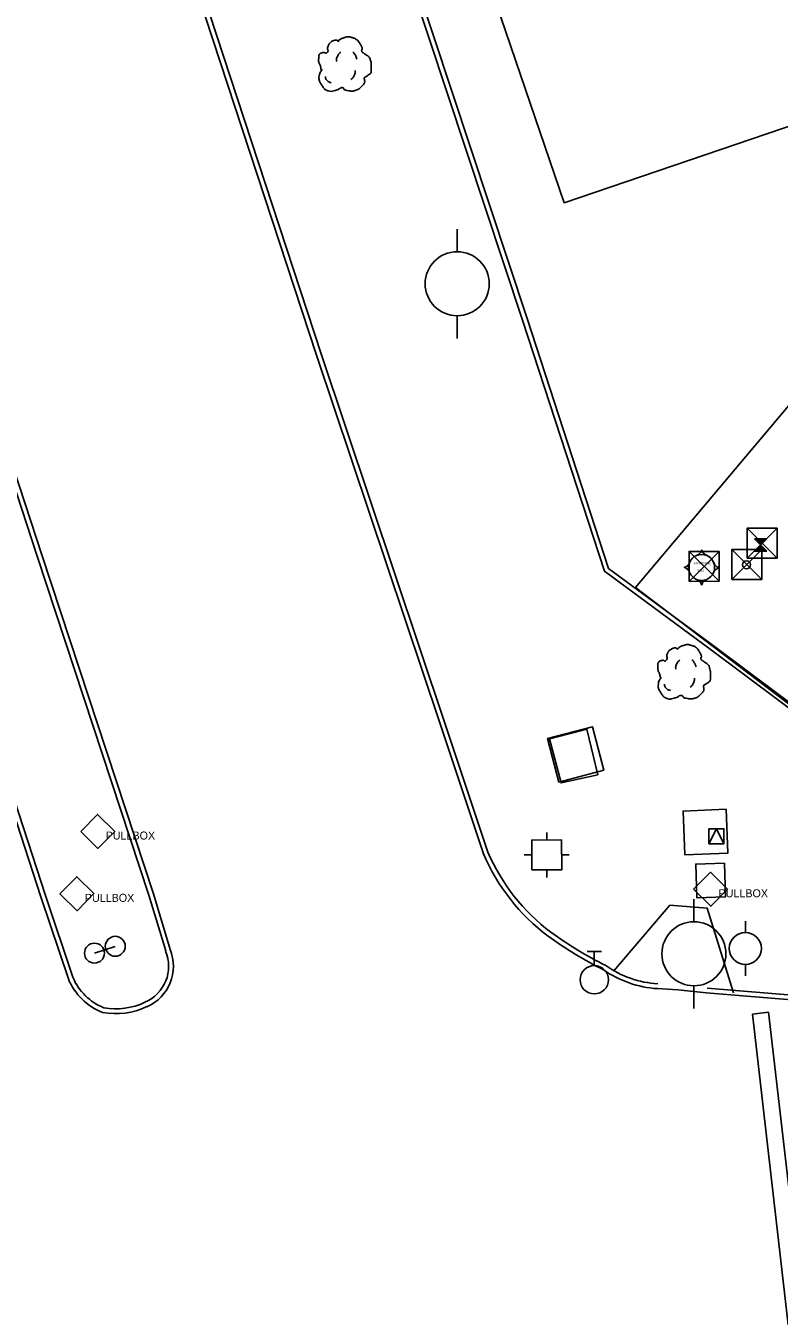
# Model space of a CAD drawing. Extents: x 2145380 to 2156929, y 139568 to 149130.
# Drawn here: x 2147292.3 to 2147386.4, y 143177.2 to 143338.4 of the extents above; entities that cross this region are included whole.
import ezdxf

# ---------------------------------------------------------------- set-up
doc = ezdxf.new("R2010")
doc.units = 0
for name, color, linetype in [('Default', 7, 'Continuous'), ('TOPO_Asphalt', 7, 'Continuous'), ('TOPO_Building', 7, 'Continuous'), ('TOPO_Concrete', 7, 'Continuous'), ('TOPO_Curb Back', 7, 'Continuous'), ('TOPO_Filler Cap', 7, 'Continuous'), ('TOPO_Fuel Pump', 7, 'Continuous'), ('TOPO_Misc', 7, 'Continuous'), ('TOPO_Misc Line', 7, 'Continuous'), ('TOPO_Monitoring Well', 7, 'Continuous'), ('TOPO_Power Pole', 7, 'Continuous'), ('TOPO_Power Pullbox', 7, 'Continuous'), ('TOPO_Sidewalk', 7, 'Continuous'), ('TOPO_Sign', 7, 'Continuous'), ('TOPO_Traffic Signal', 7, 'Continuous'), ('TOPO_Tree', 7, 'Continuous'), ('TOPO_Water Valve', 7, 'Continuous')]:
    doc.layers.add(name, color=color, linetype=linetype)

# ---------------------------------------------------------------- blocks, each defined once
blk = doc.blocks.new('POWPOL')
at = {"layer": 'TOPO_Power Pole'}
for p, q in [((0, 10.16), (0, 17.34)), ((0, -10.16), (0, -17.34))]:
    blk.add_line(p, q, dxfattribs=at)
blk.add_circle((0, 0), 10.16, dxfattribs=at)
blk = doc.blocks.new('TRFSIG')
at = {"layer": 'TOPO_Traffic Signal'}
for p, q in [((0.04, 4.66), (0.04, 7.04)), ((-4.7, -0.09), (-7.08, -0.09)), ((4.79, -0.09), (7.17, -0.09)), ((0.04, -4.83), (0.04, -7.22))]:
    blk.add_line(p, q, dxfattribs=at)
blk.add_lwpolyline([(-4.7, -4.85), (4.81, -4.83), (4.79, 4.67), (-4.72, 4.66), (-4.7, -4.85)], dxfattribs=at)
blk = doc.blocks.new('TREE')
at = {"layer": 'TOPO_Tree'}
for points in [[(-14.07, -0.4), (-14.17, 0.5), (-14.37, 1.38), (-14.6, 2.25), (-14.84, 3.17), (-15.47, 3.96), (-15.66, 4.9), (-15.8, 5.59), (-15.71, 6.31), (-15.66, 7.01), (-15.6, 7.91), (-15.72, 8.8), (-15.13, 9.66), (-14.62, 10.42), (-13.76, 10.49), (-13.02, 10.72), (-12.18, 10.98), (-11.06, 10), (-10.37, 10.72), (-9.4, 11.74), (-10.29, 13.28), (-9.84, 14.42), (-9.56, 15.15), (-9.32, 15.89), (-8.78, 16.54), (-8.18, 17.26), (-7.5, 17.68), (-6.67, 18.13), (-6.14, 18.41), (-5.61, 18.61), (-5.08, 18.66), (-4.55, 18.71), (-4.02, 18.54), (-3.49, 18.13)], [(-3.49, 17.6), (-3.07, 18.27), (-2.58, 18.8), (-1.9, 19.19), (-1.05, 19.68), (-0.19, 19.96), (0.74, 20.24), (1.62, 20.51), (2.51, 20.82), (3.39, 20.77), (4.1, 20.73), (4.8, 20.47), (5.51, 20.24), (6.43, 19.95), (7.32, 19.73), (8.15, 19.19), (9.36, 18.4), (10.02, 17.21), (10.8, 16.01), (11.24, 15.33), (11.58, 14.62), (11.86, 13.89), (12.17, 13.08), (11.37, 12.02), (11.86, 11.25), (12, 11.03), (12.18, 10.86), (12.39, 10.72), (12.91, 10.35), (13.45, 10.02), (13.97, 9.66), (14.7, 9.16), (15.41, 8.68), (16.09, 8.07), (16.7, 7.53), (16.93, 6.73), (17.15, 5.95), (17.59, 4.38), (17.71, 2.77), (17.68, 1.19), (17.65, -0.25), (17.83, -2.22), (16.62, -3.04), (15.47, -3.83), (14.31, -4.58), (13.16, -5.35)], [(-4.21, 5.09), (-4.46, 6.09), (-4.3, 7.21), (-3.84, 8.21), (-3.33, 9.34), (-2.71, 10.27), (-1.64, 10.97)], [(5.89, 11.15), (6.5, 10.68), (6.96, 10.17), (7.36, 9.5), (7.93, 8.56), (8.31, 7.6), (8.46, 6.56)], [(13.16, -5.34), (13.25, -5.81), (13.36, -6.28), (13.45, -6.75), (13.76, -8.52), (12.24, -10.03), (10.8, -11.51), (9.98, -12.34), (9.13, -12.77), (8.15, -13.1), (5.97, -13.83), (3.32, -13.56), (1.27, -13.1), (0.49, -12.92), (-0.06, -11.44), (-0.84, -11.51), (-2.04, -11.61), (-3.28, -12.78), (-4.55, -13.1), (-6.06, -13.47), (-7.77, -14.03), (-9.31, -13.62), (-11.36, -13.09), (-12.84, -11.41), (-14.07, -9.39), (-15.32, -7.35), (-15.61, -5.13), (-15.13, -3.04), (-14.87, -1.89), (-13.91, -0.75), (-13.54, 0.13)], [(-11.38, -4.46), (-11.47, -5.41), (-11.03, -6.32), (-10.09, -7.22), (-9.3, -7.97), (-8.49, -8.26), (-7.7, -8.14)], [(4.79, -6.29), (5.71, -5.66), (6.3, -4.92), (6.81, -3.91), (7.36, -2.81), (7.63, -1.7), (7.54, -0.6)]]:
    blk.add_open_spline(points, degree=3, dxfattribs=at)
blk = doc.blocks.new('POST')
at = {"layer": 'TOPO_Misc'}
for start, end in [(90, 180), (180, 270), (360, 90), (270, 0)]:
    blk.add_arc((-0.01, 0.03), 3.16, start, end, dxfattribs=at)
blk = doc.blocks.new('pulbox')
at = {"layer": 'Default'}
blk.add_lwpolyline([(-5.38, -0.01), (-0.02, 5.42), (5.4, 0.06), (0.05, -5.36), (-5.38, -0.01)], dxfattribs=at)
blk.add_text('PULLBOX', height=2.54, dxfattribs=at).set_placement((2.54, -2.54))
blk = doc.blocks.new('MONW')
at = {"layer": 'Default'}
for points in [[(-0.178, 0.372), (-0.138, 0.389), (-0.101, 0.407), (-0.063, 0.443), (-0.039, 0.474), (-0.018, 0.503), (-0.009, 0.523), (0.003, 0.552), (0.018, 0.515), (0.031, 0.488), (0.046, 0.47), (0.07, 0.441), (0.087, 0.425), (0.108, 0.407), (0.134, 0.396), (0.164, 0.385)], [(-0.369, 0.18), (-0.386, 0.141), (-0.405, 0.103), (-0.441, 0.066), (-0.471, 0.041), (-0.501, 0.021), (-0.52, 0.011), (-0.55, 0), (-0.513, -0.015), (-0.486, -0.028), (-0.467, -0.043), (-0.439, -0.068), (-0.422, -0.085), (-0.405, -0.106), (-0.394, -0.132), (-0.383, -0.162)], [(0.371, -0.189), (0.388, -0.149), (0.407, -0.111), (0.443, -0.074), (0.473, -0.05), (0.503, -0.029), (0.522, -0.019), (0.552, -0.008), (0.515, 0.007), (0.488, 0.02), (0.469, 0.035), (0.441, 0.06), (0.424, 0.077), (0.407, 0.098), (0.396, 0.124), (0.385, 0.154)], [(-0.178, -0.373), (-0.138, -0.39), (-0.101, -0.408), (-0.063, -0.444), (-0.039, -0.475), (-0.018, -0.504), (-0.009, -0.524), (0.003, -0.553), (0.018, -0.516), (0.031, -0.489), (0.046, -0.471), (0.07, -0.442), (0.087, -0.426), (0.108, -0.408), (0.134, -0.397), (0.164, -0.386)]]:
    blk.add_lwpolyline(points, dxfattribs=at)
blk.add_circle((0, 0), 0.413, dxfattribs=at)
for s, p in [('MONITORING', (-0.249, 0.103)), ('WELL', (-0.136, -0.124))]:
    blk.add_text(s, height=0.0607, dxfattribs=at).set_placement(p)
blk = doc.blocks.new('WATVAL')
at = {"layer": 'Default'}
for p, q in [((-2.25, 9), (2.25, 9)), ((0, 4.5), (0, 9))]:
    blk.add_line(p, q, dxfattribs=at)
blk.add_circle((0, 0), 4.5, dxfattribs=at)
blk = doc.blocks.new('POINT_DISPLAY')
at = {"layer": 'Default'}
blk.add_line((0, 0), (0, 0), dxfattribs=at)
blk = doc.blocks.new('gVALVE')
at = {"layer": 'Default'}
for p, q in [((0.65, 0.65), (-0.65, 0.65)), ((-0.65, -0.65), (0.65, 0.65)), ((0.65, -0.65), (-0.65, 0.65)), ((0.57, 0.62), (-0.58, 0.62)), ((-0.58, 0.62), (0, 0.04)), ((-0.51, 0.6), (0.52, 0.6)), ((0, 0.08), (-0.51, 0.6)), ((-0.44, 0.58), (0.45, 0.57)), ((0, 0.13), (-0.44, 0.58)), ((-0.37, 0.55), (0.37, 0.54)), ((0.01, 0.19), (-0.37, 0.55)), ((-0.3, 0.52), (0.3, 0.52)), ((0, 0.23), (-0.3, 0.52)), ((-0.22, 0.49), (0.23, 0.5)), ((0.01, 0.29), (-0.22, 0.49)), ((-0.15, 0.46), (0.15, 0.47)), ((0.01, 0.33), (-0.15, 0.46)), ((-0.08, 0.44), (0.09, 0.45)), ((0.01, 0.36), (-0.08, 0.44)), ((-0.04, 0.42), (0.05, 0.43)), ((0.01, 0.39), (-0.04, 0.42)), ((0, 0.04), (0.58, 0.62)), ((0.51, 0.6), (0, 0.08)), ((0.45, 0.57), (0, 0.13)), ((0.3, 0.52), (0, 0.23)), ((0.05, 0.43), (0, 0.41)), ((0.37, 0.54), (0.01, 0.19)), ((0.23, 0.49), (0.01, 0.29)), ((0.15, 0.47), (0.01, 0.33)), ((0.1, 0.45), (0.01, 0.36)), ((0.06, 0.43), (0.01, 0.39)), ((0.09, 0.45), (0.06, 0.43)), ((0.15, 0.47), (0.1, 0.45)), ((0.23, 0.5), (0.15, 0.47)), ((0.3, 0.52), (0.23, 0.49)), ((0.37, 0.54), (0.3, 0.52)), ((0.45, 0.57), (0.37, 0.54)), ((0.52, 0.6), (0.45, 0.57)), ((0.58, 0.62), (0.51, 0.6)), ((-0.65, -0.65), (0.65, -0.65)), ((-0.59, -0.62), (0, -0.03)), ((-0.59, -0.62), (-0.54, -0.6)), ((0.59, -0.63), (-0.59, -0.62)), ((-0.54, -0.6), (0, -0.08)), ((-0.54, -0.6), (-0.48, -0.58)), ((0.53, -0.6), (-0.54, -0.6)), ((-0.48, -0.58), (0, -0.13)), ((-0.47, -0.58), (-0.39, -0.55)), ((0.47, -0.58), (-0.47, -0.58)), ((-0.39, -0.55), (0, -0.18)), ((-0.39, -0.55), (-0.32, -0.53)), ((0.4, -0.55), (-0.39, -0.55)), ((-0.32, -0.53), (0, -0.22)), ((-0.31, -0.53), (-0.24, -0.51)), ((0.32, -0.53), (-0.31, -0.53)), ((-0.24, -0.51), (0, -0.28)), ((-0.24, -0.51), (-0.17, -0.49)), ((0.25, -0.5), (-0.24, -0.51)), ((-0.17, -0.49), (-0.01, -0.32)), ((-0.17, -0.48), (-0.1, -0.46)), ((0.18, -0.48), (-0.17, -0.48)), ((-0.1, -0.46), (-0.01, -0.37)), ((-0.09, -0.46), (-0.05, -0.44)), ((0.11, -0.46), (-0.09, -0.46)), ((-0.05, -0.44), (-0.01, -0.41)), ((0.04, -0.44), (-0.04, -0.44)), ((-0.01, -0.32), (0.18, -0.48)), ((-0.01, -0.37), (0.11, -0.46)), ((-0.01, -0.41), (0.04, -0.44)), ((0, -0.03), (0.59, -0.63)), ((0, -0.08), (0.53, -0.6)), ((0, -0.13), (0.47, -0.58)), ((0, -0.18), (0.4, -0.55)), ((0, -0.22), (0.32, -0.53)), ((0, -0.28), (0.25, -0.5))]:
    blk.add_line(p, q, dxfattribs=at)
blk.add_blockref('POINT_DISPLAY', (0, 0), dxfattribs=at)

msp = doc.modelspace()

# ---------------------------------------------------------------- linework, layer by layer
at = {"layer": 'TOPO_Asphalt'}
msp.add_lwpolyline([(2147371.15, 143218.12), (2147373.71, 143217.97), (2147377.31, 143217.58)], dxfattribs=at)
at = {"layer": 'TOPO_Building'}
msp.add_lwpolyline([(2147396.47, 143380.5), (2147343.76, 143362.56), (2147359.52, 143316.28), (2147412.23, 143334.22)], close=True, dxfattribs=at)
at = {"layer": 'TOPO_Concrete'}
for points in [[(2147407.53, 143238.47), (2147436.9, 143273.89), (2147397.78, 143303.06), (2147368.44, 143268.23), (2147407.53, 143238.47)], [(2147358.84, 143243.92), (2147357.43, 143249.36), (2147363.05, 143250.82), (2147364.46, 143245.38), (2147358.84, 143243.92)], [(2147363.71, 143244.8), (2147359.13, 143243.8), (2147357.68, 143249.32), (2147362.33, 143250.51), (2147363.71, 143244.8)], [(2147374.59, 143234.83), (2147374.36, 143240.29), (2147379.73, 143240.51), (2147379.96, 143235.05), (2147374.59, 143234.83)], [(2147379.55, 143233.78), (2147379.67, 143229.58), (2147376.08, 143229.47), (2147375.95, 143233.67), (2147379.55, 143233.78)]]:
    msp.add_lwpolyline(points, dxfattribs=at)
at = {"layer": 'TOPO_Curb Back'}
for p, q in [((2147279.68, 143314.95), (2147293.72, 143272.12)), ((2147280.25, 143315.14), (2147294.29, 143272.31)), ((2147294.19, 143229.56), (2147278.21, 143278.52)), ((2147294.76, 143229.75), (2147278.78, 143278.69)), ((2147293.72, 143272.12), (2147307.65, 143229.79)), ((2147294.29, 143272.31), (2147308.22, 143229.97)), ((2147297.61, 143219.32), (2147294.19, 143229.56)), ((2147298.17, 143219.53), (2147294.76, 143229.75)), ((2147307.65, 143229.79), (2147309.76, 143222.81)), ((2147308.22, 143229.97), (2147310.32, 143223.01))]:
    msp.add_line(p, q, dxfattribs=at)
for points in [[(2147517.02, 143239.1), (2147482.38, 143238.34), (2147439.31, 143237.85), (2147408.44, 143237.55), (2147377.76, 143260.51), (2147364.56, 143270.24), (2147354.31, 143301.63), (2147333.23, 143365.36), (2147326.82, 143385.52), (2147326.46, 143411.36), (2147326.23, 143416.01)], [(2147517, 143239.7), (2147482.37, 143238.94), (2147439.3, 143238.45), (2147408.63, 143238.16), (2147378.12, 143260.99), (2147365.07, 143270.61), (2147354.88, 143301.82), (2147333.8, 143365.55), (2147327.41, 143385.62), (2147327.06, 143411.38), (2147326.83, 143415.99)], [(2147293.8, 143402.61), (2147300.88, 143382.17), (2147313.77, 143342.42), (2147328.59, 143297.23), (2147344.02, 143251.18), (2147349.44, 143234.94)], [(2147294.36, 143402.8), (2147301.45, 143382.36), (2147314.34, 143342.61), (2147329.16, 143297.42), (2147344.59, 143251.38), (2147350, 143235.15)], [(2147377.36, 143218.18), (2147403.62, 143216.02), (2147433.38, 143213.03), (2147447.37, 143211.78), (2147492.61, 143210.69), (2147509.18, 143209.95)], [(2147377.31, 143217.58), (2147403.56, 143215.42), (2147433.33, 143212.43), (2147447.34, 143211.18), (2147492.58, 143210.09), (2147509.15, 143209.36)]]:
    msp.add_lwpolyline(points, dxfattribs=at)
for centre, radius, start, end in [((2147372.8, 143244.95), 25.41, 203.189, 232.9922), ((2147372.8, 143244.95), 24.81, 203.246, 232.9766), ((2147387.43, 143266.29), 51.27, 234.2901, 243.3365), ((2147387.43, 143266.29), 50.67, 234.2978, 243.3859), ((2147305.2, 143220.92), 4.93, 293.547, 22.5261), ((2147305.2, 143220.92), 5.53, 293.6433, 22.2073), ((2147372.02, 143231.35), 12.67, 234.8757, 266.317), ((2147304.67, 143222.26), 7.65, 202.6402, 248.5564), ((2147304.67, 143222.26), 7.05, 202.8146, 248.092), ((2147372.02, 143231.35), 13.27, 235.07, 266.317), ((2147303.54, 143224.1), 8.51, 259.8549, 295.3006), ((2147303.54, 143224.1), 9.11, 259.4676, 295.2436)]:
    msp.add_arc(centre, radius, start, end, dxfattribs=at)
at = {"layer": 'TOPO_Filler Cap'}
msp.add_circle((2147382.29, 143271.06), 0.5, dxfattribs=at)
at = {"layer": 'TOPO_Misc'}
for p, q in [((2147382.36, 143275.62), (2147386.11, 143271.88)), ((2147375.12, 143272.73), (2147378.87, 143268.99)), ((2147380.47, 143272.97), (2147384.22, 143269.23))]:
    msp.add_line(p, q, dxfattribs=at)
for points in [[(2147382.37, 143271.88), (2147386.11, 143271.88), (2147386.11, 143275.63), (2147382.36, 143275.62), (2147382.37, 143271.88), (2147386.11, 143275.63)], [(2147375.13, 143268.98), (2147378.87, 143268.99), (2147378.86, 143272.73), (2147375.12, 143272.73), (2147375.13, 143268.98), (2147378.86, 143272.73)], [(2147380.47, 143269.22), (2147384.22, 143269.23), (2147384.21, 143272.97), (2147380.47, 143272.97), (2147380.47, 143269.22), (2147384.21, 143272.97)], [(2147377.6, 143236.21), (2147379.47, 143236.21), (2147379.47, 143238.09), (2147377.6, 143238.08), (2147377.6, 143236.21), (2147378.54, 143238.08), (2147379.47, 143236.21)]]:
    msp.add_lwpolyline(points, dxfattribs=at)
at = {"layer": 'TOPO_Misc Line'}
msp.add_lwpolyline([(2147389.93, 143172.79), (2147385.03, 143215.16), (2147383.04, 143214.93), (2147388.02, 143171.39)], close=True, dxfattribs=at)
at = {"layer": 'TOPO_Sidewalk'}
msp.add_lwpolyline([(2147365.73, 143220.35), (2147372.72, 143228.52), (2147377.39, 143228.18), (2147380.68, 143217.6)], dxfattribs=at)
at = {"layer": 'TOPO_Sign'}
msp.add_lwpolyline([(2147300.87, 143222.53), (2147303.47, 143223.39)], dxfattribs=at)

# ---------------------------------------------------------------- block references
at = {"layer": 'TOPO_Fuel Pump', "xscale": 1.1811000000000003, "yscale": 1.1811000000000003}
msp.add_blockref('gVALVE', (2147384.07, 143273.53), dxfattribs=at)
msp.add_blockref('gVALVE', (2147384.07, 143273.53), dxfattribs=at)
at = {"layer": 'TOPO_Misc', "xscale": 0.39370000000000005, "yscale": 0.3937000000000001}
for p in [(2147303.47, 143223.39), (2147300.87, 143222.53)]:
    msp.add_blockref('POST', p, dxfattribs=at)
at = {"layer": 'TOPO_Monitoring Well', "xscale": 3.9370000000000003, "yscale": 3.9370000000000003}
msp.add_blockref('MONW', (2147376.68, 143270.72), dxfattribs=at)
at = {"layer": 'TOPO_Power Pole'}
for p, xscale, yscale in [((2147346.16, 143306.16), 0.39370000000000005, 0.3937000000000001), ((2147375.72, 143222.46), 0.39370000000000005, 0.3937000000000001), ((2147382.14, 143223.13), 0.19685000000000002, 0.19685000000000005)]:
    msp.add_blockref('POWPOL', p, dxfattribs=dict(at, xscale=xscale, yscale=yscale))
at = {"layer": 'TOPO_Power Pullbox', "xscale": 0.39370000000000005, "yscale": 0.3937000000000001}
for p in [(2147301.27, 143237.73), (2147377.8, 143230.52), (2147298.67, 143229.95)]:
    msp.add_blockref('pulbox', p, dxfattribs=at)
at = {"layer": 'TOPO_Traffic Signal', "xscale": 0.39370000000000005, "yscale": 0.3937000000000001}
msp.add_blockref('TRFSIG', (2147357.32, 143234.84), dxfattribs=at)
at = {"layer": 'TOPO_Tree', "xscale": 0.19685000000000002, "yscale": 0.19685000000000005}
for p in [(2147331.95, 143332.92), (2147374.3, 143257)]:
    msp.add_blockref('TREE', p, dxfattribs=at)
at = {"layer": 'TOPO_Water Valve', "xscale": 0.39370000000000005, "yscale": 0.3937000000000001}
msp.add_blockref('WATVAL', (2147363.28, 143219.22), dxfattribs=at)

doc.saveas('drawing.dxf')
